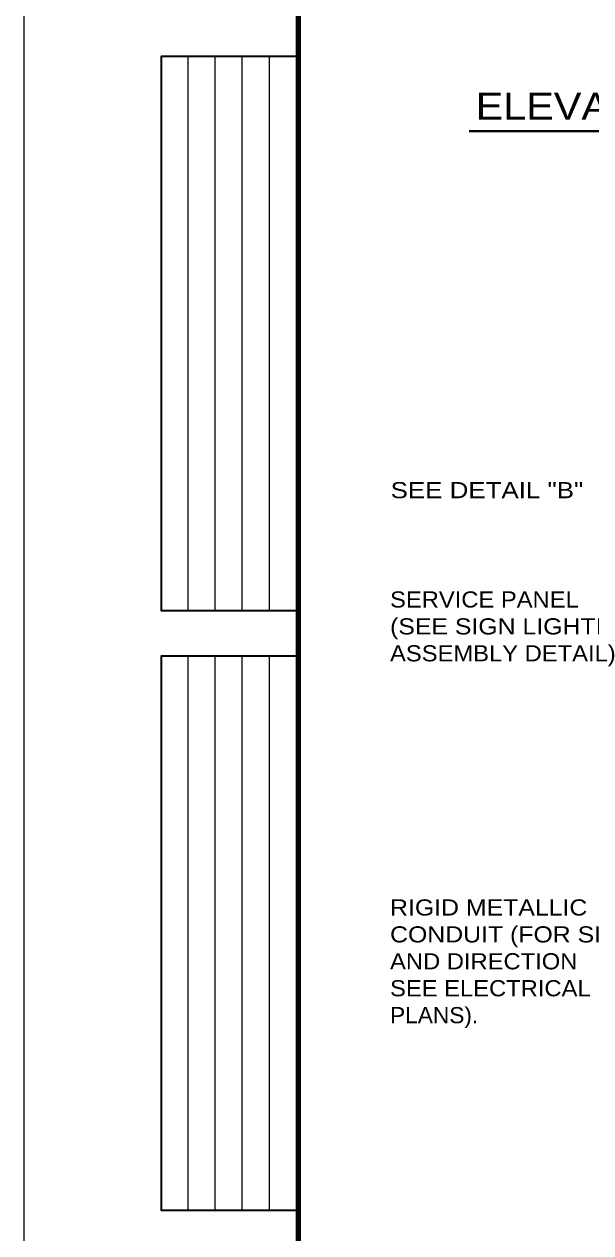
# Model space of a CAD drawing. Extents: x 312601.858 to 312602.699, y 144420.109 to 144420.704.
# Drawn here: x 312601.8578 to 312601.9631, y 144420.232 to 144420.4564 of the extents above; entities that cross this region are included whole.
import ezdxf
from ezdxf.enums import TextEntityAlignment as Align

# ---------------------------------------------------------------- set-up
doc = ezdxf.new("R2010")
doc.units = 0
doc.header["$LTSCALE"] = 0.0012
for name, color, linetype, lineweight in [('1', 7, 'Continuous', 25), ('2', 7, 'Continuous', 25), ('39', 7, 'Continuous', 13), ('60', 7, 'Continuous', 25)]:
    doc.layers.add(name, color=color, linetype=linetype, lineweight=lineweight)

msp = doc.modelspace()

# ---------------------------------------------------------------- linework, layer by layer
at = {"layer": '1', "lineweight": 40}
msp.add_line((312601.9405, 144420.4366), (312602.1364, 144420.4366), dxfattribs=at)
at = {"layer": '39', "lineweight": 25}
msp.add_line((312601.8578, 144420.1095), (312601.8578, 144420.7035), dxfattribs=at)
at = {"layer": '39', "lineweight": 158}
msp.add_line((312601.9088, 144420.1247), (312601.9088, 144420.6645), dxfattribs=at)
at = {"layer": '60'}
for p, q in [((312601.8883, 144420.3475), (312601.8883, 144420.4505)), ((312601.8933, 144420.3475), (312601.8933, 144420.4505)), ((312601.8983, 144420.3475), (312601.8983, 144420.4505)), ((312601.9034, 144420.3475), (312601.9034, 144420.4505)), ((312601.8883, 144420.2361), (312601.8883, 144420.3391)), ((312601.8933, 144420.2361), (312601.8933, 144420.3391)), ((312601.8983, 144420.2361), (312601.8983, 144420.3391)), ((312601.9034, 144420.2361), (312601.9034, 144420.3391))]:
    msp.add_line(p, q, dxfattribs=at)
at = {"layer": '60', "lineweight": 35}
for points in [[(312601.9084, 144420.3475), (312601.8833, 144420.3475), (312601.8833, 144420.4505), (312601.9084, 144420.4505)], [(312601.9084, 144420.2361), (312601.8833, 144420.2361), (312601.8833, 144420.3391), (312601.9084, 144420.3391)]]:
    msp.add_lwpolyline(points, dxfattribs=at)

# ---------------------------------------------------------------- texts
at = {"layer": '1', "width": 1.2}
msp.add_text('SEE DETAIL "B"', height=0.003, dxfattribs=at).set_placement((312601.9438, 144420.3684), align=Align.CENTER)
at = {"layer": '1'}
for s, width, p in [('SERVICE PANEL', 1.1, (312601.9258, 144420.3481)), ('(SEE SIGN LIGHTING', 1.15, (312601.9258, 144420.3431)), ('ASSEMBLY DETAIL)', 1.1, (312601.9258, 144420.3381)), ('RIGID METALLIC', 1.15, (312601.9258, 144420.2909)), ('CONDUIT (FOR SIZE', 1.15, (312601.9258, 144420.2859)), ('AND DIRECTION', 1.1, (312601.9258, 144420.2809)), ('SEE ELECTRICAL', 1.1, (312601.9258, 144420.2759)), ('PLANS).', 1.05, (312601.9258, 144420.2709))]:
    msp.add_text(s, height=0.003, dxfattribs=dict(at, width=width)).set_placement(p)
at = {"layer": '2', "width": 1.15}
msp.add_text('ELEVATION - TYPICAL CANTILEVER SIGN SUPPORT', height=0.005, dxfattribs=at).set_placement((312601.9417, 144420.4387))

doc.saveas('drawing.dxf')
